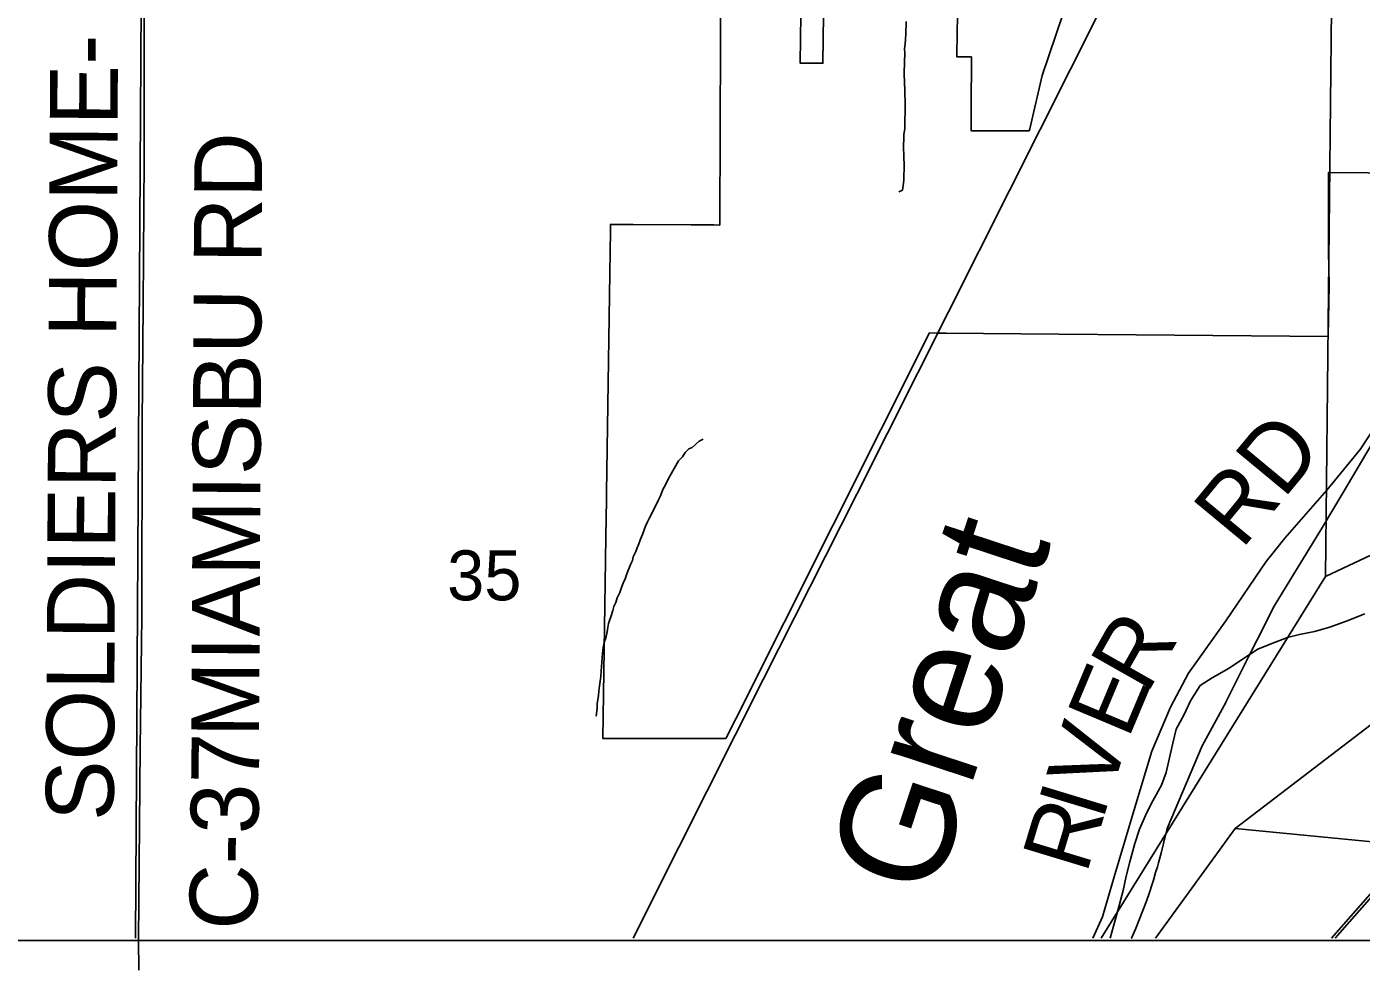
# Model space of a CAD drawing. Extents: x 0 to 34, y 0 to 22.
# Drawn here: x 3.924 to 5.042, y 13.975 to 14.765 of the extents above; entities that cross this region are included whole.
import ezdxf

# ---------------------------------------------------------------- set-up
doc = ezdxf.new("R2010")
doc.units = 0
for name, color, linetype in [('GM_X_County_Road', 7, 'Continuous'), ('GM_X_County_Road_Text', 7, 'Continuous'), ('GM_X_Interchange_Ramps', 7, 'Continuous'), ('GM_X_Major_River', 7, 'Continuous'), ('GM_X_Major_River_Text', 7, 'Continuous'), ('GM_X_Minor_River', 7, 'Continuous'), ('GM_X_Rail_Line', 7, 'Continuous'), ('GM_X_Section', 7, 'Continuous'), ('GM_X_Section_Text', 7, 'Continuous'), ('GM_X_State_Shield', 7, 'Continuous'), ('SH_Data', 7, 'Continuous')]:
    doc.layers.add(name, color=color, linetype=linetype)

msp = doc.modelspace()

# ---------------------------------------------------------------- linework, layer by layer
at = {"layer": 'GM_X_County_Road'}
for points in [[(4.0179, 13.9751), (4.0177, 14.0006), (4.0192, 14.1613), (4.0205, 14.2715), (4.0208, 14.4334), (4.0216, 14.5324), (4.0225, 14.6549), (4.0225, 14.783)], [(4.8173, 14.0019), (4.8254, 14.0198), (4.8352, 14.0534), (4.8525, 14.1115), (4.8668, 14.1587), (4.8825, 14.1956), (4.8975, 14.2241), (4.9289, 14.2678), (4.9626, 14.3176), (4.9782, 14.337), (5.0133, 14.3773), (5.0414, 14.4112), (5.0645, 14.4464), (5.0781, 14.4734), (5.0994, 14.5098), (5.1207, 14.5466), (5.1284, 14.5669), (5.1384, 14.6066), (5.1524, 14.667), (5.154, 14.6739)], [(5.0204, 14.0019), (5.0323, 14.0156), (5.0596, 14.0465), (5.0735, 14.0622), (5.0842, 14.074), (5.0952, 14.0846), (5.1121, 14.0986), (5.1374, 14.1177), (5.1811, 14.1508), (5.211, 14.1734), (5.2573, 14.2093), (5.275, 14.2231), (5.2927, 14.2362), (5.302, 14.243), (5.3074, 14.2462)]]:
    msp.add_lwpolyline(points, dxfattribs=at)
at = {"layer": 'GM_X_Interchange_Ramps'}
for points in [[(4.5055, 14.7755), (4.505, 14.6575), (4.5049, 14.6223), (4.5048, 14.6034), (4.5048, 14.5993), (4.4999, 14.5994), (4.4808, 14.5995), (4.4321, 14.5998), (4.4131, 14.5999), (4.4131, 14.5945), (4.4125, 14.5586), (4.4098, 14.3753), (4.4097, 14.3691), (4.4093, 14.3385), (4.409, 14.3184), (4.4082, 14.2622), (4.4068, 14.1692), (4.4332, 14.1692), (4.5079, 14.1692), (4.5098, 14.1692), (4.5181, 14.1858), (4.6805, 14.509), (4.6875, 14.5089), (4.6929, 14.5088), (4.6944, 14.5088), (4.757, 14.5082), (5.0146, 14.5059), (5.0146, 14.5066), (5.0153, 14.5484), (5.0149, 14.5777), (5.0148, 14.582), (5.0147, 14.6432), (5.0152, 14.6432), (5.1473, 14.6421)], [(4.5916, 14.7753), (4.5912, 14.7349), (4.5722, 14.7348), (4.5722, 14.7351), (4.5727, 14.7753)], [(4.7922, 14.7756), (4.7749, 14.7247), (4.7647, 14.6798), (4.764, 14.6783), (4.7287, 14.6783), (4.7154, 14.6783), (4.7155, 14.7015), (4.7156, 14.7358), (4.7156, 14.7402), (4.7035, 14.7401), (4.7035, 14.7423), (4.7039, 14.7756)], [(5.0588, 14.4286), (5.0271, 14.3752), (5.0099, 14.3462), (4.9939, 14.3202), (4.9917, 14.3166), (4.9702, 14.2816), (4.9692, 14.28), (4.9627, 14.267), (4.9623, 14.2662), (4.9482, 14.2381), (4.9291, 14.2002), (4.929, 14.2001), (4.9091, 14.1631), (4.8795, 14.094), (4.8793, 14.0929), (4.8766, 14.0813), (4.8746, 14.0732), (4.8741, 14.0713), (4.8724, 14.0651), (4.8714, 14.0618), (4.87, 14.057), (4.8681, 14.0507), (4.8676, 14.049), (4.8667, 14.0465), (4.865, 14.041), (4.8622, 14.0331), (4.8593, 14.0252), (4.8563, 14.0174), (4.8531, 14.0096), (4.8498, 14.0019), (4.8498, 14.0019)]]:
    msp.add_lwpolyline(points, dxfattribs=at)
at = {"layer": 'GM_X_Major_River'}
msp.add_lwpolyline([(5.0452, 14.2736), (5.0306, 14.2678), (5.016, 14.2624), (5.003, 14.2588), (4.9904, 14.2564), (4.9805, 14.254), (4.9659, 14.2482), (4.9555, 14.2442), (4.9428, 14.2357), (4.9316, 14.2283), (4.9174, 14.2202), (4.9073, 14.2136), (4.8991, 14.2008), (4.8939, 14.1895), (4.8872, 14.1771), (4.8843, 14.1654), (4.8822, 14.1556), (4.8788, 14.1408), (4.8748, 14.1302), (4.8677, 14.1171), (4.8625, 14.1073), (4.8565, 14.0934), (4.8525, 14.0813), (4.8484, 14.0661), (4.8454, 14.054), (4.8429, 14.0419), (4.8384, 14.0253), (4.8347, 14.0121), (4.8318, 14.0019)], dxfattribs=at)
at = {"layer": 'GM_X_Minor_River'}
for points in [[(4.6608, 14.7698), (4.6606, 14.7592), (4.66, 14.7508), (4.6595, 14.747), (4.6598, 14.7436), (4.6594, 14.7272), (4.6595, 14.7177), (4.6598, 14.7135), (4.6597, 14.7104), (4.6602, 14.7013), (4.6597, 14.6803), (4.6591, 14.675), (4.6588, 14.6628), (4.6591, 14.659)], [(4.6591, 14.659), (4.659, 14.6552), (4.6593, 14.6506), (4.6589, 14.6365), (4.6584, 14.6324), (4.6579, 14.6286), (4.6549, 14.6271)], [(4.4909, 14.4201), (4.4874, 14.4183), (4.4816, 14.4131), (4.4789, 14.412), (4.4758, 14.4087), (4.4734, 14.4053), (4.4703, 14.4019), (4.4679, 14.3978), (4.4639, 14.391), (4.4615, 14.3865), (4.459, 14.3813), (4.4574, 14.3783), (4.4562, 14.3756), (4.455, 14.3726), (4.4534, 14.3692), (4.4518, 14.3654), (4.4458, 14.3542), (4.4442, 14.3508), (4.4425, 14.347), (4.4401, 14.3402), (4.4384, 14.3361), (4.4368, 14.3323), (4.4356, 14.3289), (4.4344, 14.3259), (4.4323, 14.3214), (4.4315, 14.3183), (4.4303, 14.3157), (4.4291, 14.3127), (4.4278, 14.3093), (4.4266, 14.3063), (4.4254, 14.3029), (4.4238, 14.2995), (4.4225, 14.2957), (4.4209, 14.2915), (4.4189, 14.287), (4.4176, 14.2832), (4.416, 14.2799), (4.4152, 14.2765), (4.4135, 14.2712), (4.4123, 14.2681), (4.4115, 14.2655), (4.4106, 14.2606), (4.4101, 14.2568), (4.4092, 14.2537), (4.408, 14.2496), (4.4071, 14.2454), (4.4066, 14.2405), (4.4061, 14.2371), (4.406, 14.2329), (4.4056, 14.2295), (4.4055, 14.2257), (4.405, 14.2211), (4.404, 14.2135), (4.4035, 14.209), (4.403, 14.2052), (4.4026, 14.2017), (4.4021, 14.1987), (4.402, 14.1953), (4.4016, 14.1922), (4.4011, 14.1881)]]:
    msp.add_lwpolyline(points, dxfattribs=at)
at = {"layer": 'GM_X_Rail_Line'}
for points in [[(5.0173, 14.0019), (5.072, 14.0644), (5.1295, 14.1143), (5.176, 14.1513), (5.2792, 14.2282), (5.3136, 14.2527), (5.4907, 14.3356), (5.7836, 14.4807), (6.1751, 14.7018), (6.2931, 14.7677), (6.5502, 14.9097), (6.5918, 14.9396), (6.8599, 15.0815), (6.9063, 15.1008), (7.0305, 15.1642), (7.127, 15.2232), (7.2771, 15.3236), (7.3717, 15.417), (7.5681, 15.606)], [(4.4322, 14.0019), (4.4704, 14.0782), (4.5412, 14.2186), (4.6196, 14.374), (4.8244, 14.781), (4.9948, 15.1204), (5.1022, 15.3337)]]:
    msp.add_lwpolyline(points, dxfattribs=at)
at = {"layer": 'GM_X_Section'}
for points in [[(3.0071, 14.0019), (3.0289, 14.7963), (4.0198, 14.784), (4.0152, 14.0019)], [(4.0152, 14.0019), (4.0198, 14.784), (5.0174, 14.7806), (5.0124, 14.305), (4.8242, 14.0019)]]:
    msp.add_lwpolyline(points, dxfattribs=at)
for points in [[(5.0174, 14.7806), (5.5176, 14.7755), (5.3974, 14.4862), (5.0124, 14.305)], [(4.9365, 14.094), (5.5231, 14.5424), (5.4797, 14.0411)]]:
    msp.add_lwpolyline(points, close=True, dxfattribs=at)
at = {"layer": 'GM_X_State_Shield'}
msp.add_lwpolyline([(5.4762, 14.0019), (5.4797, 14.0411), (4.9365, 14.094), (4.8698, 14.0019)], dxfattribs=at)
at = {"layer": 'SH_Data'}
msp.add_line((2, 14), (9, 14), dxfattribs=at)

# ---------------------------------------------------------------- texts
at = {"layer": 'GM_X_County_Road_Text'}
for s, height, rotation, p in [('SOLDIERS HOME-', 0.056818, 89.6699, (3.9968, 14.1001)), ('MIAMISBU RD', 0.056818, 89.6951, (4.1187, 14.1703)), ('RD', 0.05682, 50.3726, (4.942, 14.3268)), ('R', 0.0568, 60.4822, (4.8626, 14.2055)), ('E', 0.0568, 67.1998, (4.8469, 14.1679)), ('V', 0.0568, 72.277, (4.8322, 14.1215)), ('C-37', 0.05682, 89.3129, (4.1171, 14.0088)), ('I', 0.0568, 73.1228, (4.8255, 14.0994)), ('R', 0.0568, 73.1389, (4.8119, 14.0548))]:
    msp.add_text(s, height=height, rotation=rotation, dxfattribs=at).set_placement(p)
at = {"layer": 'GM_X_Major_River_Text'}
msp.add_text('Great', height=0.09469, rotation=71.7843, dxfattribs=at).set_placement((4.6836, 14.033))
at = {"layer": 'GM_X_Section_Text'}
msp.add_text('35', height=0.04186, rotation=0, dxfattribs=at).set_placement((4.2763, 14.285))

doc.saveas('drawing.dxf')
